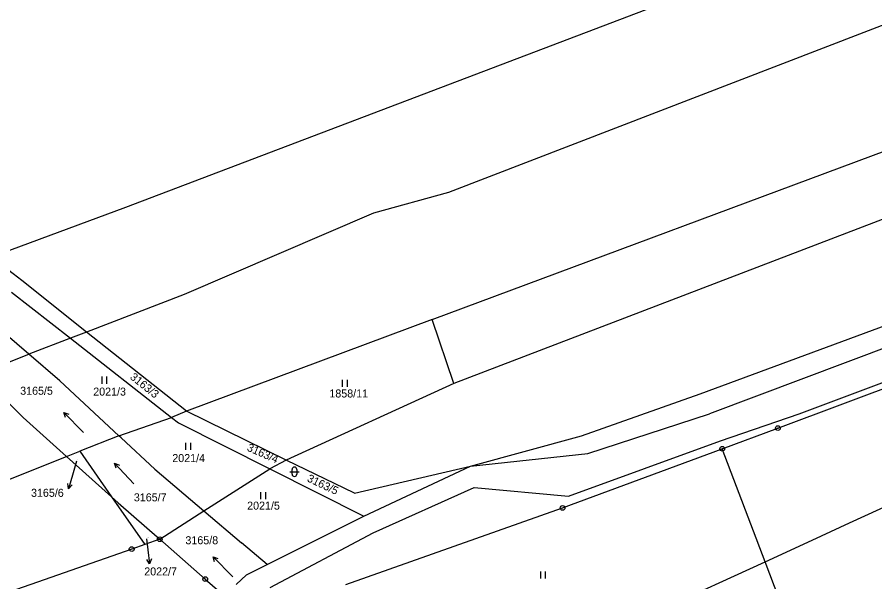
# Model space of a CAD drawing. Extents: x -736345 to -729997, y -1130177 to -1122501.
# Drawn here: x -732950.1 to -732767.9, y -1127200.4 to -1127080.5 of the extents above; entities that cross this region are included whole.
import ezdxf

# ---------------------------------------------------------------- set-up
doc = ezdxf.new("R2010")
doc.units = 0
for name, color, linetype in [('Vrstva 1', 7, 'Continuous'), ('Vrstva 16', 7, 'Continuous'), ('Vrstva 18', 7, 'Continuous'), ('Vrstva 25', 7, 'Continuous')]:
    doc.layers.add(name, color=color, linetype=linetype)

msp = doc.modelspace()

# ---------------------------------------------------------------- linework, layer by layer
at = {"layer": 'Vrstva 1'}
for points in [[(-732717.47, -1127063.37), (-732858.45, -1127117.68)], [(-732784.11, -1127066.52), (-732927.05, -1127120.88)], [(-732804.95, -1127160.47), (-732633.62, -1127097.18)], [(-732636.04, -1127102.02), (-732802.98, -1127164.69)], [(-732861.91, -1127144.72), (-732758.48, -1127106.19)], [(-732783.95, -1127164.73), (-732640.83, -1127111.04)], [(-732740.03, -1127113.42), (-732857.33, -1127158.31)], [(-732858.45, -1127117.68), (-732874.38, -1127122.09)], [(-732927.05, -1127120.88), (-732955.58, -1127131.47)], [(-732874.38, -1127122.09), (-732914.59, -1127139.37)], [(-732949.12, -1127136.39), (-732955.58, -1127131.47)], [(-732935.32, -1127147.35), (-732949.12, -1127136.39)], [(-732951.3, -1127138.86), (-732938.76, -1127148.67)], [(-732914.59, -1127139.37), (-732935.32, -1127147.35)], [(-732947.58, -1127152.07), (-732960.95, -1127140.67)], [(-732861.91, -1127144.72), (-732914.13, -1127164.19)], [(-732857.33, -1127158.31), (-732861.91, -1127144.72)], [(-732935.32, -1127147.35), (-732938.76, -1127148.67)], [(-732914.13, -1127164.19), (-732935.32, -1127147.35)], [(-732788.46, -1127167.76), (-732733.2, -1127147.08)], [(-732938.76, -1127148.67), (-732947.58, -1127152.07)], [(-732938.76, -1127148.67), (-732917.3, -1127165.47)], [(-732953.88, -1127154.5), (-732947.58, -1127152.07)], [(-732940.99, -1127157.69), (-732947.58, -1127152.07)], [(-732958.13, -1127156.14), (-732948.8, -1127165.49)], [(-732928.45, -1127169.37), (-732940.99, -1127157.69)], [(-732857.33, -1127158.31), (-732892.9, -1127174.53)], [(-732830.15, -1127169.42), (-732804.95, -1127160.47)], [(-732914.13, -1127164.19), (-732917.3, -1127165.47)], [(-732892.9, -1127174.53), (-732914.13, -1127164.19)], [(-732828.86, -1127173.15), (-732802.98, -1127164.69)], [(-732800.65, -1127170.43), (-732783.95, -1127164.73)], [(-732948.8, -1127165.49), (-732939.58, -1127173.77)], [(-732928.45, -1127169.37), (-732917.3, -1127165.47)], [(-732917.3, -1127165.47), (-732915.81, -1127166.63)], [(-732915.81, -1127166.63), (-732896.43, -1127176.39)], [(-732800.28, -1127172.14), (-732788.46, -1127167.76)], [(-732928.45, -1127169.37), (-732936.77, -1127172.64)], [(-732928, -1127169.79), (-732928.45, -1127169.37)], [(-732920.8, -1127176.49), (-732928, -1127169.79)], [(-732853.75, -1127175.85), (-732830.15, -1127169.42)], [(-732834.21, -1127184.71), (-732800.28, -1127172.14)], [(-732832.94, -1127182.2), (-732800.65, -1127170.43)], [(-732791.19, -1127196.14), (-732800.28, -1127172.14)], [(-732966.08, -1127184.36), (-732939.58, -1127173.77)], [(-732939.58, -1127173.77), (-732936.77, -1127172.64)], [(-732939.58, -1127173.77), (-732930.04, -1127182.34)], [(-732936.77, -1127172.64), (-732930.04, -1127182.34)], [(-732853.75, -1127175.85), (-732828.86, -1127173.15)], [(-732892.9, -1127174.53), (-732896.43, -1127176.39)], [(-732878.41, -1127181.58), (-732892.9, -1127174.53)], [(-732878.41, -1127181.58), (-732853.75, -1127175.85)], [(-732876.42, -1127186.47), (-732853.75, -1127175.85)], [(-732920.8, -1127176.49), (-732910.39, -1127185.34)], [(-732910.39, -1127185.34), (-732896.43, -1127176.39)], [(-732896.43, -1127176.39), (-732876.42, -1127186.47)], [(-732874.42, -1127190.01), (-732852.96, -1127180.38)], [(-732852.96, -1127180.38), (-732832.94, -1127182.2)], [(-732930.04, -1127182.34), (-732922.99, -1127192.49)], [(-732930.04, -1127182.34), (-732928.61, -1127183.62)], [(-732773.22, -1127187.9), (-732760.99, -1127182.27)], [(-732928.61, -1127183.62), (-732919.78, -1127191.36)], [(-732880.22, -1127200.99), (-732834.21, -1127184.71)], [(-732919.78, -1127191.36), (-732910.39, -1127185.34)], [(-732910.39, -1127185.34), (-732902.44, -1127192.09)], [(-732897, -1127196.72), (-732876.42, -1127186.47)], [(-732781.21, -1127191.58), (-732773.22, -1127187.9)], [(-732896.33, -1127201.61), (-732874.42, -1127190.01)], [(-732919.78, -1127191.36), (-732922.99, -1127192.49)], [(-732919.78, -1127191.36), (-732910.12, -1127199.82)], [(-732897, -1127196.72), (-732902.44, -1127192.09)], [(-732791.19, -1127196.14), (-732781.21, -1127191.58)], [(-732925.75, -1127193.46), (-732954.51, -1127203.55)], [(-732922.99, -1127192.49), (-732925.75, -1127193.46)], [(-732901.39, -1127198.91), (-732897, -1127196.72)], [(-732813.17, -1127206.19), (-732791.19, -1127196.14)], [(-732770.46, -1127250.79), (-732791.19, -1127196.14)], [(-732903.54, -1127200.95), (-732901.39, -1127198.91)], [(-732910.12, -1127199.82), (-732907.05, -1127202.5)]]:
    msp.add_lwpolyline(points, dxfattribs=at)
at = {"layer": 'Vrstva 16'}
for points in [[(-732937.45, -1127174.76), (-732938.31, -1127177.77)], [(-732922.58, -1127191.27), (-732922.29, -1127193.6)]]:
    msp.add_lwpolyline(points, dxfattribs=at)
at = {"layer": 'Vrstva 25'}
for points in [[(-732932.047, -1127158.315), (-732932.047, -1127156.815)], [(-732931.013, -1127158.315), (-732931.013, -1127156.815)], [(-732880.957, -1127159.015), (-732880.957, -1127157.515)], [(-732879.923, -1127159.015), (-732879.923, -1127157.515)], [(-732939.828, -1127165.484), (-732940.172, -1127164.421), (-732939.115, -1127164.784)], [(-732935.968, -1127168.699), (-732940.172, -1127164.421)], [(-732914.217, -1127172.385), (-732914.217, -1127170.885)], [(-732913.183, -1127172.385), (-732913.183, -1127170.885)], [(-732929.079, -1127176.289), (-732929.395, -1127175.216), (-732928.348, -1127175.607)], [(-732925.305, -1127179.604), (-732929.395, -1127175.216)], [(-732892.16, -1127177.02), (-732890.16, -1127177.02)], [(-732891.66, -1127177.52), (-732891.66, -1127176.52)], [(-732890.66, -1127176.52), (-732890.66, -1127177.52)], [(-732938.31, -1127177.77), (-732939.141, -1127180.652)], [(-732938.384, -1127179.83), (-732939.141, -1127180.652), (-732939.345, -1127179.552)], [(-732898.317, -1127182.835), (-732898.317, -1127181.335)], [(-732897.283, -1127182.835), (-732897.283, -1127181.335)], [(-732922.29, -1127193.6), (-732921.93, -1127196.578)], [(-732921.554, -1127195.525), (-732921.93, -1127196.578), (-732922.546, -1127195.645)], [(-732908.124, -1127196.164), (-732908.473, -1127195.102), (-732907.414, -1127195.459)], [(-732904.247, -1127199.358), (-732908.473, -1127195.102)], [(-732838.857, -1127199.725), (-732838.857, -1127198.225)], [(-732837.823, -1127199.725), (-732837.823, -1127198.225)]]:
    msp.add_lwpolyline(points, dxfattribs=at)
for centre, radius in [((-732788.46, -1127167.76), 0.5), ((-732788.46, -1127167.76), 0.032), ((-732800.28, -1127172.14), 0.5), ((-732800.28, -1127172.14), 0.032), ((-732834.21, -1127184.71), 0.5), ((-732834.21, -1127184.71), 0.032), ((-732919.78, -1127191.36), 0.5), ((-732919.78, -1127191.36), 0.032), ((-732925.75, -1127193.46), 0.5), ((-732925.75, -1127193.46), 0.032), ((-732910.12, -1127199.82), 0.5), ((-732910.12, -1127199.82), 0.032)]:
    msp.add_circle(centre, radius, dxfattribs=at)
for centre, start, end in [((-732891.16, -1127176.52), 0.10099, 180.00143), ((-732891.16, -1127177.52), 180.10243, 0.00286)]:
    msp.add_arc(centre, 0.5, start, end, dxfattribs=at)

# ---------------------------------------------------------------- texts
at = {"layer": 'Vrstva 16'}
for s, p in [('3165/6', (-732947.137, -1127182.35)), ('2022/7', (-732923.08, -1127199.04))]:
    msp.add_text(s, height=1.7, dxfattribs=at).set_placement(p)
at = {"layer": 'Vrstva 18'}
for s, rotation, p in [('3163/3', 321.30256, (-732926.249, -1127157.169)), ('3163/4', 336.40267, (-732901.397, -1127172.487)), ('3163/5', 334.60266, (-732888.634, -1127178.996))]:
    msp.add_text(s, height=1.7, rotation=rotation, dxfattribs=at).set_placement(p)
for s, height, p in [('3165/5', 1.7, (-732949.44, -1127160.67)), ('2021/3', 1.7, (-732933.92, -1127160.85)), ('1858/11', 1.7, (-732883.75, -1127161.25)), ('2021/4', 1.7, (-732917.12, -1127174.97)), ('3165/6', 0.1, (-732937.25, -1127174.56)), ('3165/7', 1.7, (-732925.29, -1127183.31)), ('2021/5', 1.7, (-732901.22, -1127185.07)), ('2022/7', 0.1, (-732922.38, -1127191.07)), ('3165/8', 1.7, (-732914.33, -1127192.42))]:
    msp.add_text(s, height=height, dxfattribs=at).set_placement(p)

doc.saveas('drawing.dxf')
